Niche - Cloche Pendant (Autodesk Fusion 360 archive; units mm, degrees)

design "Cloche" references "Niche - Chief Architect - Luxe Single Pendant Cordset", "Cloche", "Luxe Single Pendant Cordset - 4ft Standard"
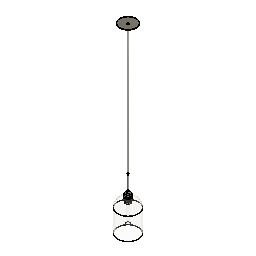
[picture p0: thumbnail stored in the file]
external_derived "ExternalDerived1" bodies "Cloche"
external_derived "ExternalDerived2" bodies "Socket Body", "Shade Ring", "Shade Ring +Collar", "Socket", "Body1", "Metal Strain Relief", "Fabric Cord (1)", "Stem (Threaded)"
align "Align1"
external_derived "ExternalDerived3" bodies "T9-Bulb"
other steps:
derived_base_feature "Derived Base Feature1" bodies "Cloche"
derived_base_feature "Derived Base Feature2" bodies "Socket Body", "Shade Ring", "Shade Ring +Collar", "Socket", "Body1", "Metal Strain Relief", "Fabric Cord (1)", "Stem (Threaded)"
derived_base_feature "Derived Base Feature3" bodies "T9-Bulb"
named bodies: "Cloche", "Socket Body", "Shade Ring", "Shade Ring +Collar", "Socket", "Body1", "Metal Strain Relief", "Fabric Cord (1)", "Stem (Threaded)", "Cap (Threaded)", "5M Set Screw", "T9-Bulb"

design "Luxe Single Pendant Cordset - 4ft Standard" references "Luxe Canopy - Single Pendant Cordset"
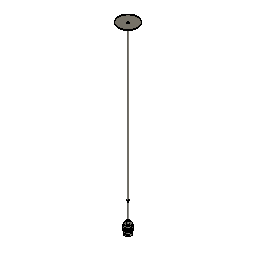
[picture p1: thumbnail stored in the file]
external_derived "ExternalDerived2" bodies "Cap (Threaded)"
move "Move1"
move "Move2"
offset_faces "OffsetFaces1" distance 1051.56
move "Move3"
move "Move4"
move "Move5"
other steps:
derived_base_feature "Derived Base Feature9" bodies "Socket Body", "Shade Ring", "Shade Ring +Collar", "Socket"
derived_base_feature "Derived Base Feature10" bodies "Body1"
derived_base_feature "Derived Base Feature12" bodies "Metal Strain Relief"
derived_base_feature "Derived Base Feature13" bodies "Fabric Cord (1)"
derived_base_feature "Derived Base Feature14" bodies "Stem (Threaded)"
derived_base_feature "Derived Base Feature15" bodies "Cap 9Threaded)", "Cap (Threaded)"
named bodies: "Socket Body", "Shade Ring", "Shade Ring +Collar", "Socket", "Metal Strain Relief", "Fabric Cord (1)", "Stem (Threaded)", "Cap 9Threaded)", "Body1", "Cap (Threaded)", "5M Set Screw"

design "Luxe Canopy - Single Pendant Cordset" references "M5 Set Screw", "Canopy Mounting Bar", "Canopy Mounting Bar Screw", "Plastic Strain Relief", "Luxe Cordset"
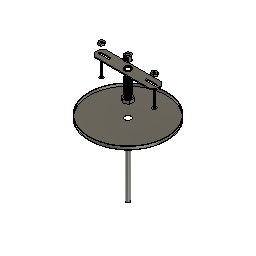
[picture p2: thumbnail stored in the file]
sketch "Sketch1" plane through (0, 0, 0) normal (0, 0, 1) x axis (1, 0, 0)
  circle C1 centre (0, 0) radius 63.5
  point P1 (0, 0)
  point P2 (0, 0)
  coincident P1 P2
  dimension "d1" diameter C1 = 127
extrude "Extrude1" new body sketch "Sketch1" along normal blind 5.08
shell "Shell1" innerThickness 0.762
hole "Hole1" HoleDepth 35.56 HoleDiameter 10.16 TipAngle 118
component_from_bodies "Body->Comp1"
component_insert "Component Insert1"
component_insert "Component Insert2"
component_insert "Component Insert3"
sketch "Sketch2" plane through (0, 0, 0) normal (0, 0, 1) x axis (1, 0, 0)
  circle C1 centre (0, 0) radius 3.175
  point P1 (0, 0)
  point P2 (0, 0)
  coincident P1 P2
  dimension "d8" diameter C1 = 6.35
extrude "Extrude2" new body sketch "Sketch2" along normal blind 127 and against normal blind 127 bodies "Fabric Cord"
component_insert "Component Insert4"
component_insert "Component Insert5"
position "Position1"
sketch "Sketch3" plane through (0, 0, 0.762) normal (0, 0, 1) x axis (-1, 0, 0)
  circle C1 centre (-0.0475, 0.2257) radius 5.08
  circle C2 centre (0, 0) radius 62.738
  circle C3 centre (0, 0) radius 4.826
  concentric C2 C3
  dimension "d13" diameter C3 = 9.652
extrude "Extrude3" new body sketch "Sketch3" profile of C3 along normal blind 25.4 bodies "Threaded Nipple"
shell "Shell2" innerThickness 1.27
thread "Thread1"
sketch "Sketch5" plane through (0, 0, 127) normal (0, 0, 1) x axis (-1, 0, 0)
  line L1 (-6.8191, 3.937) -> (0, 7.874)
  line L2 (-6.8191, -3.937) -> (-6.8191, 3.937)
  line L3 (0, -7.874) -> (-6.8191, -3.937)
  line L4 (6.8191, -3.937) -> (0, -7.874)
  line L5 (6.8191, 3.937) -> (6.8191, -3.937)
  line L6 (0, 7.874) -> (6.8191, 3.937)
  circle C1 centre (0, 0) radius 3.175
  point P2 (0, 0)
  point P9 (0, 0)
  point P3 (0, 7.874)
  coincident P2 P9
  dimension "d20" distance P3 P9 = 7.874
extrude "Extrude4" new body sketch "Sketch5" along normal blind 5.08 bodies "Hex Nut"
move "Move1"
thread "Thread2"
move "Move2" TranslateX 0 TranslateY 0 TranslateZ -55.88
move "Move3" TranslateX 0 TranslateY 0 TranslateZ 60.96
position "Position2"
sketch "Sketch6" plane through (0, 0, 0) normal (0, 0, 1) x axis (1, 0, 0)
  circle C1 centre (0, 0) radius 9.525
  point P1 (0, 0)
  point P2 (0, 0)
  coincident P1 P2
  dimension "d29" diameter C1 = 19.05
extrude "Extrude5" new body sketch "Sketch6" along normal blind 16.129 bodies "Metal Strain Relief"
move "Move4" TranslateX 0 TranslateY 0 TranslateZ -86.36
hole "Hole2" HoleDepth 10.16 HoleDiameter 5.08 TipAngle 118
hole "Hole3" HoleDepth 4.064 HoleDiameter 7.62 TipAngle 180
hole "Hole4" HoleDepth 12.192 HoleDiameter 9.144 TipAngle 180
thread "Thread3" ThreadOffset 0 ThreadLength 6.096
move "Move1" TranslateX 0 TranslateY 0 TranslateZ 68.58
move "Move5" TranslateX 0 TranslateY 0 TranslateZ 138.43
component_insert "Component Insert6"
external_derived "ExternalDerived1" bodies "5M Set Screw"
move "Move6" TranslateX 0 TranslateY 0 TranslateZ -185.42
copy_paste_bodies "CopyPasteBodies1"
move "Move7" TranslateX 0 TranslateY 0 TranslateZ -12.7
offset_faces "OffsetFaces1" distance -152.4
move "Move8"
component_from_bodies "Body->Comp2"
component_from_bodies "Body->Comp3"
component_from_bodies "Body->Comp4"
component_from_bodies "Body->Comp5"
hole "Hole1" HoleDepth 25.4 HoleDiameter 6.35 TipAngle 180
sketch "Sketch7" plane through (0, 0, 0) normal (0, 0, 1) x axis (1, 0, 0)
  line L1 (49.784, 3.9595) -> (52.07, 0)
  line L2 (45.212, 3.9595) -> (49.784, 3.9595)
  line L3 (42.926, 0) -> (45.212, 3.9595)
  line L4 (45.212, -3.9595) -> (42.926, 0)
  line L5 (49.784, -3.9595) -> (45.212, -3.9595)
  line L6 (52.07, 0) -> (49.784, -3.9595)
  point P2 (52.07, 0)
  point P8 (47.498, 0)
  dimension "d63" distance P2 P8 = 4.572
extrude "Extrude6" new body sketch "Sketch7" along normal blind 3.175 bodies "Mounting Hex Nut"
hole "Hole5" HoleDepth 25.4 HoleDiameter 3.81 TipAngle 180
thread "Thread4"
move "Move9"
component_from_bodies "Body->Comp6"
copy_paste "CopyPaste1"
move "Move10"
derived_base_feature "Derived Base Feature3" bodies "Stem (Threaded)", "Cap 9Threaded)"
move "Move11"
component_from_bodies "Body->Comp7"
component_from_bodies "Body->Comp8"
component_from_bodies "Body->Comp9"
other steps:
base_feature "Base Feature1"
base_feature "Base Feature1" bodies "Stem (Threaded)"
base_feature "Base Feature1" bodies "Cap 9Threaded)"
base_feature "Base Feature1" bodies "Fabric Cord"
base_feature "Base Feature1" bodies "Metal Strain Relief"
base_feature "Base Feature1" bodies "Mounting Hex Nut"
base_feature "Base Feature1" bodies "Hex Nut"
base_feature "Base Feature1" bodies "Fabric Cord (1)"
base_feature "Base Feature1" bodies "Threaded Nipple"
derived_base_feature "Derived Base Feature1" bodies "Socket Body", "Shade Ring", "Shade Ring +Collar", "Socket", "Rigid Stem"
derived_base_feature "Derived Base Feature2" bodies "5M Set Screw"
base_feature "Base Feature1" bodies "Fabric Cord", "Fabric Cord (1)"
create_component "CreateComponent1"
remove_body "RemoveBody1"
create_component "CreateComponent2"
remove_body "RemoveBody2"
create_component "CreateComponent3"
remove_body "RemoveBody3"
create_component "CreateComponent4"
remove_body "RemoveBody4"
create_component "CreateComponent5"
remove_body "RemoveBody5"
create_component "CreateComponent6"
remove_body "RemoveBody6"
create_component "CreateComponent7"
remove_body "RemoveBody7"
create_component "CreateComponent8"
remove_body "RemoveBody8"
create_component "CreateComponent9"
remove_body "RemoveBody9"
named bodies: "Fabric Cord", "Threaded Nipple", "Hex Nut", "Metal Strain Relief", "Socket Body", "Shade Ring", "Shade Ring +Collar", "Socket", "Rigid Stem", "5M Set Screw", "Fabric Cord (1)", "Mounting Hex Nut", "Stem (Threaded)", "Cap 9Threaded)"

design "M5 Set Screw"
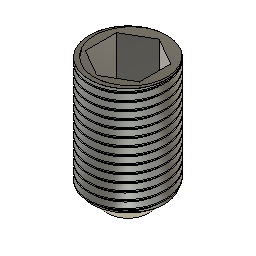
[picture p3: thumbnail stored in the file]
sketch "Sketch1" plane through (0, 0, 0) normal (0, 0, 1) x axis (1, 0, 0)
  circle C1 centre (0, 0) radius 2.5
  point P1 (0, 0)
  point P2 (0, 0)
  coincident P1 P2
  dimension "d1" diameter C1 = 5
extrude "Extrude1" new body sketch "Sketch1" along normal blind 8
sketch "Sketch2" plane through (0, 0, 8) normal (0, 0, 1) x axis (-1, 0, 0)
  line L1 (-1.7321, 1) -> (0, 2)
  line L2 (-1.7321, -1) -> (-1.7321, 1)
  line L3 (0, -2) -> (-1.7321, -1)
  line L4 (1.7321, -1) -> (0, -2)
  line L5 (1.7321, 1) -> (1.7321, -1)
  line L6 (0, 2) -> (1.7321, 1)
  circle C1 centre (0, 0) radius 2.5
  point P2 (0, 0)
  point P9 (0, 0)
  coincident P2 P9
extrude "Extrude2" cut sketch "Sketch2" profile of L1 L2 L3 L4 L5 L6 against normal blind 3
thread "Thread1" ThreadOffset 0.99 ThreadLength 7
chamfer "Chamfer1" distance 1.15

design "Luxe Cordset" references "M5 Set Screw"
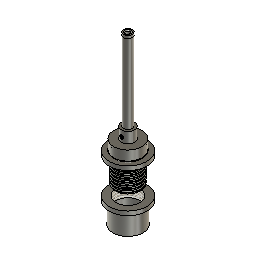
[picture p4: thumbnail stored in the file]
sketch "Sketch1" plane through (0, 0, 0) normal (0, 0, 1) x axis (1, 0, 0)
  circle C1 centre (0, 0) radius 20.6
  point P1 (0, 0)
  point P2 (0, 0)
  coincident P1 P2
  dimension "d11" diameter C1 = 41.2
extrude "Extrude1" new body sketch "Sketch1" along normal blind 14 bodies "Socket Body"
sketch "Sketch2" plane through (0, 0, 14) normal (0, 0, 1) x axis (-1, 0, 0)
  circle C1 centre (0, 0) radius 20.6
  circle C2 centre (0, 0) radius 9.6
  concentric C1 C2
  dimension "d3" diameter C2 = 19.2
extrude "Extrude2" add sketch "Sketch2" profile of C2 along normal blind 15.75
sketch "Sketch3" plane through (0, 0, 29.75) normal (0, 0, 1) x axis (-1, 0, 0)
  circle C1 centre (0, 0) radius 9.6
  circle C2 centre (0, 0) radius 5.75
  concentric C1 C2
  dimension "d6" diameter C2 = 11.5
extrude "Extrude3" new body sketch "Sketch3" profile of C2 along normal blind 114 bodies "Rigid Stem"
move "Move1"
sketch "Sketch4" plane through (0, 0, 203.75) normal (0, 0, 1) x axis (-1, 0, 0)
  circle C1 centre (0, 0) radius 5.75
  circle C2 centre (0, 0) radius 27.5
  dimension "d10" diameter C2 = 55
extrude "Extrude4" new body sketch "Sketch4" profile of C2 along normal blind 6 bodies "Shade Ring"
hole "Hole1" HoleDepth 25 HoleDiameter 42.75 TipAngle 118
sketch "Sketch5" plane through (0, 0, 0) normal (0, 0, 1) x axis (1, 0, 0)
  circle C1 centre (0, 0) radius 22
  point P1 (0, 0)
  point P2 (0, 0)
  coincident P1 P2
  dimension "d18" diameter C1 = 44
move "Move2"
copy_paste_bodies "CopyPasteBodies1"
move "Move3"
sketch "Sketch6" plane through (0, 0, 60) normal (0, 0, -1) x axis (1, 0, 0)
  circle C1 centre (0, 0) radius 20.6
  circle C2 centre (0, 0) radius 21.375
  circle C3 centre (0, 0) radius 20
  concentric C1 C2
  concentric C1 C3
  dimension "d21" diameter C2 = 42.75
  dimension "d24" diameter C3 = 40
cylinder_primitive "CylinderPrimitive1" Height 8 Diameter 42.75
thread "Thread1"
thread "Thread3"
hole "Hole2" HoleDepth 18 HoleDiameter 39 TipAngle 180
move "Move4"
move "Move5"
move "Move6"
hole "Hole3" HoleDepth 114 HoleDiameter 7.6 TipAngle 180
derived_base_feature "Derived Base Feature" bodies "Socket"
move "Move7"
scale "Scale1" ScaleX 1.2 ScaleY 1.2
move "Move8"
sketch "Sketch8" plane through (0, 0, -23.9827) normal (0, 0, -1) x axis (1, 0, 0)
  circle C1 centre (0, -0.036) radius 27.5
  circle C2 centre (0, -0.036) radius 22
  circle C3 centre (0, -0.036) radius 19.5
  dimension "d36" diameter C2 = 44
  dimension "d42" = -2.5
extrude "Extrude7" add sketch "Sketch8" profile of C2 C3 along normal blind 30
offset_faces "OffsetFaces1" distance 2.75
offset_faces "OffsetFaces2" distance -9
thread "Thread2"
move "Move9"
move "Move10"
move "Move11"
scale "Scale2" ScaleZ 1.2
move "Move12"
move "Move13"
move "Move14"
move "Move15"
move "Move16"
split_face "SplitFace1"
move "Move17"
move "Move18"
move "Move19"
move "Move20"
move "Move21"
move "Move22"
move "Move23"
move "Move24"
move "Move25"
move "Move26"
move "Move27"
thread "Thread4"
move "Move28"
move "Move29"
move "Move30"
hole "Hole4" HoleDepth 21 HoleDiameter 39.35 TipAngle 180
hole "Hole5" HoleDepth 9 HoleDiameter 5 TipAngle 180
move "Move31"
move "Move32"
hole "Hole6" HoleDepth 20 HoleDiameter 10 TipAngle 180
move_face "MoveFace3"
move "Move33"
move "Move34"
move "Move35"
move "Move36"
move "Move37"
thread "Thread5" ThreadOffset 0 ThreadLength 6
thread "Thread6" ThreadOffset 0 ThreadLength 6
move "Move38"
move "Move39"
move "Move40"
move "Move41"
component_insert "Component Insert"
thread "Thread7" ThreadOffset 0.5 ThreadLength 5.337
chamfer "Chamfer1" distance 0.5 distance 0.35
sketch "Sketch12" plane through (0, 0, 0) normal (0, 0, 1) x axis (1, 0, 0)
  circle C1 centre (0, 0) radius 6.35
  dimension "d60" diameter C1 = 12.7
extrude "Extrude8" new body sketch "Sketch12" along normal blind 115 bodies "Stem (Threaded)"
hole "Hole7" HoleDepth 115 HoleDiameter 9.65 TipAngle 118
thread "Thread8" ThreadOffset 0 ThreadLength 12.5
thread "Thread9" ThreadOffset 0 ThreadLength 12.5
sketch "Sketch13" plane through (0, 0, 0) normal (0, 0, 1) x axis (1, 0, 0)
  circle C1 centre (0, 0) radius 6.35
  point P1 (0, 0)
  point P2 (0, 0)
  coincident P1 P2
  dimension "d70" diameter C1 = 12.7
extrude "Extrude9" new body sketch "Sketch13" along normal blind 4 bodies "Cap 9Threaded)"
sketch "Sketch14" plane through (0, 0, 4) normal (0, 0, 1) x axis (-1, 0, 0)
  circle C1 centre (0, 0) radius 6.35
  circle C2 centre (0, 0) radius 4.5
  concentric C1 C2
  dimension "d73" diameter C2 = 9
extrude "Extrude10" add sketch "Sketch14" profile of C2 against normal blind 14
thread "Thread10"
hole "Hole8" HoleDepth 115 HoleDiameter 6.5 TipAngle 118 CSDiameter 9 CSAngle 90
move "Move42"
move "Move43"
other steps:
base_feature "Base Feature" bodies "Shade Ring +Collar"
named bodies: "Socket Body", "Shade Ring", "Shade Ring +Collar", "Socket", "Rigid Stem", "Stem (Threaded)", "Cap 9Threaded)"

design "Niche - Chief Architect - Luxe Single Pendant Cordset"
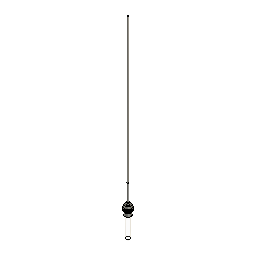
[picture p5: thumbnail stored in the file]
derived_base_feature "Derived Base Feature" bodies "Socket Body", "Shade Ring", "Shade Ring +Collar", "Socket", "Canopy", "Metal Strain Relief", "Fabric Cord (1)", "Stem (Threaded)"
remove_body "RemoveBody1"
remove_body "RemoveBody2"
split "Split1" bodies "Socket Body (1)"
remove_body "RemoveBody3"
align "Align1"
hole "Hole1" HoleDepth 19.05 HoleDiameter 8.89 TipAngle 118
combine "Combine1" bodies "Shade Ring"
split "Split2" bodies "Socket (1)"
remove_body "RemoveBody4"
split "Split3" bodies "Fabric Cord (1) (1)"
remove_body "RemoveBody5"
combine "Combine2" bodies "Socket Body"
align "Align2"
combine "Combine3" bodies "Metal Strain Relief"
sketch "Sketch1" plane through (0, 0, 0) normal (0, 1, 0) x axis (1, 0, 0)
  line L1 (13.1098, 24.9049) -> (-12.2902, 24.9049)
  line L2 (18.1898, 37.1766) -> (18.1898, 29.9849)
  line L3 (-17.3702, 29.9849) -> (-17.3702, 36.7132)
  line L4 (0, 132.969) -> (0, 24.9049)
  arc A1 centre (0, 86.36) radius 46.609 clockwise from (-22.6031, 45.5985) to (23.276, 45.979)
  arc A2 centre (-27.5302, 36.7132) radius 10.16 clockwise from (-22.6031, 45.5985) to (-17.3702, 36.7132)
  arc A3 centre (28.3498, 37.1766) radius 10.16 clockwise from (18.1898, 37.1766) to (23.276, 45.979)
  arc A4 centre (-12.2902, 29.9849) radius 5.08 clockwise from (-12.2902, 24.9049) to (-17.3702, 29.9849)
  arc A5 centre (13.1098, 29.9849) radius 5.08 clockwise from (18.1898, 29.9849) to (13.1098, 24.9049)
  point P5 (18.1898, 43.4469)
  point P3 (-17.3702, 24.9049)
  point P4 (18.1898, 24.9049)
  point P18 (0, 24.9049)
  point P19 (0, 132.969)
  horizontal L1
  vertical L2
  vertical L3
  tangent A1 A2
  tangent L3 A2
  coincident P5 L2
  coincident P5 A1
  tangent L2 A3
  tangent A1 A3
  equal A2 A3
  coincident P3 L1
  coincident P3 L3
  tangent L1 A4
  tangent L3 A4
  coincident P4 L1
  coincident P4 L2
  tangent L1 A5
  tangent L2 A5
  coincident L1 P18
  coincident A1 P19
  perpendicular L1 L4
  dimension "d4" diameter A1 = 93.218
  dimension "d5" distance P3 P4 = 35.56
  dimension "d6" distance P4 P5 = 18.542
  dimension "d7" radius A2 = 10.16
  dimension "d8" radius A4 = 5.08
  dimension "d9" radius A5 = 5.08
revolve "Revolve1" sketch "Sketch1" AlongAngle 360 bodies "G30-Bulb"
move "Move1"
sketch "Sketch2" plane through (0, 0, 0) normal (0, 1, 0) x axis (1, 0, 0)
  line L1 (12.7, 0) -> (-12.7, 0)
  line L2 (12.7, 152.4) -> (12.7, 0)
  line L3 (-12.7, 0) -> (-12.7, 152.4)
  line L4 (0, 165.1) -> (0, 0)
  arc A1 centre (0, 152.4) radius 12.7 clockwise from (-12.7, 152.4) to (12.7, 152.4)
  point P1 (0, 0)
  point P7 (0, 0)
  point P8 (0, 165.1)
  horizontal L1
  vertical L2
  vertical L3
  coincident P1 P7
  midpoint A1 P8
  perpendicular L1 L4
revolve "Revolve2" sketch "Sketch2" AlongAngle 360 bodies "T9-Bulb"
move "Move2"
sketch "Sketch3" plane through (0, 0, 0) normal (0, 1, 0) x axis (1, 0, 0)
  line L1 (12.7, 0) -> (-12.7, 0)
  line L2 (12.7, 254) -> (12.7, 0)
  line L3 (-12.7, 0) -> (-12.7, 254)
  line L4 (0, 266.7) -> (0, 0)
  arc A1 centre (0, 254) radius 12.7 clockwise from (-12.7, 254) to (12.7, 254)
  point P1 (0, 0)
  point P7 (0, 0)
  point P8 (0, 266.7)
  horizontal L1
  vertical L2
  vertical L3
  coincident P1 P7
  midpoint A1 P8
  perpendicular L1 L4
revolve "Revolve3" sketch "Sketch3" AlongAngle 360 bodies "T8-Bulb"
move "Move3"
move "Move4"
move "Move5"
sketch "Sketch4" plane through (0, 0, 0) normal (0, 1, 0) x axis (1, 0, 0)
  line L1 (15.875, -8.763) -> (-15.875, -8.763)
  line L2 (15.875, 22.987) -> (15.875, -8.763)
  line L3 (-15.875, 22.987) -> (15.875, 22.987)
  line L4 (-15.875, -8.763) -> (-15.875, 22.987)
  line L5 (0, 22.987) -> (0, -8.763)
  point P6 (0, -8.763)
  point P7 (0, 22.987)
  point P2 (-15.875, -8.763)
  point P3 (15.875, -8.763)
  point P5 (-15.875, 22.987)
  horizontal L1
  vertical L2
  horizontal L3
  vertical L4
  midpoint L1 P6
  midpoint L3 P7
  dimension "d13" distance P2 P3 = 31.75
  dimension "d14" distance P2 P5 = 31.75
revolve "Revolve4" sketch "Sketch4" AlongAngle 360 bodies "Bulb Extender"
move "Move6"
sketch "Sketch5" plane through (0, 0, 0) normal (0, 1, 0) x axis (1, 0, 0)
  line L1 (-12.7, 35.56) -> (12.7, 35.56)
  line L2 (-12.7, 5.08) -> (-12.7, 35.56)
  line L3 (12.7, 5.08) -> (-12.7, 5.08)
  line L4 (12.7, 35.56) -> (12.7, 5.08)
  line L5 (-12.7, 5.08) -> (12.7, 35.56)
  line L6 (12.7, 5.08) -> (-12.7, 35.56)
  line L7 (0, 35.56) -> (0, 5.08)
  point P6 (0, 20.32)
  point P7 (0, 5.08)
  point P8 (0, 35.56)
  horizontal L1
  perpendicular L1 L2
  parallel L1 L3
  parallel L2 L4
  coincident L5 P6
  coincident L6 P6
  midpoint L3 P7
  midpoint L1 P8
revolve "Revolve5" sketch "Sketch5" AlongAngle 360 bodies "Y-Spliter"
sketch "Sketch6" plane through (0, 0, 0) normal (0, 1, 0) x axis (1, 0, 0)
  line L1 (-55.88, 64.9514) -> (-21.59, 64.9514)
  line L2 (-55.88, 35.7414) -> (-55.88, 64.9514)
  line L3 (-21.59, 35.7414) -> (-55.88, 35.7414)
  line L4 (-21.59, 64.9514) -> (-21.59, 35.7414)
  line L5 (-55.88, 35.7414) -> (-21.59, 64.9514)
  line L6 (-21.59, 35.7414) -> (-55.88, 64.9514)
  line L7 (-38.735, 64.9514) -> (-38.735, 35.7414)
  point P6 (-38.735, 50.3464)
  point P7 (-38.735, 35.7414)
  point P8 (-38.735, 64.9514)
  point P4 (-55.88, 35.7414)
  point P5 (-21.59, 35.7414)
  point P2 (-21.59, 64.9514)
  horizontal L1
  perpendicular L1 L2
  parallel L1 L3
  parallel L2 L4
  coincident L5 P6
  coincident L6 P6
  midpoint L3 P7
  midpoint L1 P8
  dimension "d17" distance P4 P5 = 34.29
  dimension "d18" distance P2 P5 = 29.21
revolve "Revolve6" sketch "Sketch6" AlongAngle 360
chamfer "Chamfer1" distance 7.62
move "Move7"
mirror "Mirror1" mirrorStitchTolerance 0.1016
move "Move8"
combine "Combine4"
move "Move9"
sketch "Sketch7" plane through (0, 0, 0) normal (0, 1, 0) x axis (1, 0, 0)
  line L1 (-15.24, 40.64) -> (-15.24, 48.1816)
  line L2 (12.7, 38.1) -> (-12.7, 38.1)
  line L3 (15.24, 48.1816) -> (15.24, 40.64)
  line L4 (0, 100.1623) -> (0, 38.1)
  arc A1 centre (0, 76.2) radius 23.9623 clockwise from (-19.7282, 62.5988) to (19.7282, 62.5988)
  arc A2 centre (-40.64, 48.1816) radius 25.4 clockwise from (-19.7282, 62.5988) to (-15.24, 48.1816)
  arc A3 centre (40.64, 48.1816) radius 25.4 clockwise from (15.24, 48.1816) to (19.7282, 62.5988)
  arc A4 centre (-12.7, 40.64) radius 2.54 clockwise from (-12.7, 38.1) to (-15.24, 40.64)
  arc A5 centre (12.7, 40.64) radius 2.54 clockwise from (15.24, 40.64) to (12.7, 38.1)
  point P15 (0, 38.1)
  point P16 (0, 100.1623)
  parallel L1 L3
  tangent A1 A2
  tangent L1 A2
  tangent A1 A3
  tangent L3 A3
  tangent L1 A4
  tangent L2 A4
  tangent L2 A5
  tangent L3 A5
  midpoint L2 P15
  midpoint A1 P16
  perpendicular L2 L4
  dimension "d23" radius A2 = 25.4
  dimension "d24" radius A3 = 25.4
  dimension "d25" radius A4 = 2.54
  dimension "d26" radius A5 = 2.54
revolve "Revolve7" sketch "Sketch7" AlongAngle 360 bodies "A15-Bulb"
move "Move10"
copy_paste_bodies "CopyPasteBodies1"
copy_paste_bodies "CopyPasteBodies2"
move "Move11"
mirror "Mirror2" mirrorStitchTolerance 0.1016 bodies "A15-Bulb (1) (1)"
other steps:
base_feature "Base Feature1" bodies "Y-Spliter", "Bulb Extender", "Y-Spliter (1)", "Bulb Extender (1)"
base_feature "Base Feature2" bodies "A15-Bulb", "A15-Bulb (1)"
named bodies: "Socket Body", "Shade Ring", "Shade Ring +Collar", "Socket", "Canopy", "Metal Strain Relief", "Fabric Cord (1)", "Stem (Threaded)", "Adapter", "5M Set Screw", "Body1 (1)", "Socket Body (1)", "Socket (1)", "Fabric Cord (1) (1)", "G30-Bulb", "T9-Bulb", "T8-Bulb", "Bulb Extender", "Y-Spliter", "A15-Bulb", "Y-Spliter (1)", "Bulb Extender (1)", "A15-Bulb (1)", "A15-Bulb (1) (1)"

design "Plastic Strain Relief"
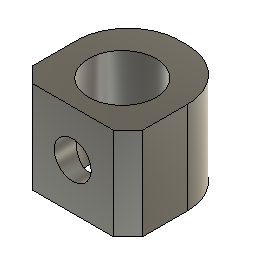
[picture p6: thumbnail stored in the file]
base_feature "Base Feature" bodies "strainrelief"
named bodies: "strainrelief"

design "Cloche"
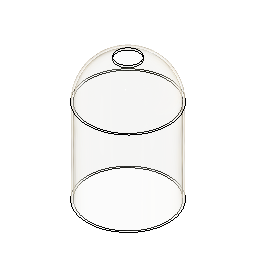
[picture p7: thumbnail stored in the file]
sketch "Sketch1" plane through (0, 0, 0) normal (0, 1, 0) x axis (1, 0, 0)
  line L1 (0, 171.45) -> (0, -82.55)
  line L2 (82.55, 171.45) -> (82.55, 0)
  line L3 (-82.55, 171.45) -> (-82.55, 0)
  line L4 (78.74, 171.45) -> (78.74, 0)
  line L5 (-78.74, 171.45) -> (-78.74, 0)
  line L6 (-78.74, 171.45) -> (-82.55, 171.45)
  line L7 (82.55, 171.45) -> (78.74, 171.45)
  line L8 (22.225, -75.5383) -> (22.225, -79.5019)
  line L9 (-22.225, -75.5383) -> (-22.225, -79.5019)
  arc A1 centre (0, 0) radius 82.55 clockwise from (-22.225, -79.5019) to (-82.55, 0)
  arc A2 centre (0, 0) radius 82.55 clockwise from (82.55, 0) to (22.225, -79.5019)
  arc A3 centre (0, 0) radius 78.74 clockwise from (-22.225, -75.5383) to (-78.74, 0)
  arc A4 centre (0, 0) radius 78.74 clockwise from (78.74, 0) to (22.225, -75.5383)
  point P2 (0, -82.55)
  point P14 (22.225, -75.5383)
  coincident P2 A1
  parallel L1 L2
  parallel L1 L3
  perpendicular L2 L6
  collinear L6 L7
  parallel L1 L9
  parallel L1 L8
  coincident P14 A3
  concentric A1 A2
  parallel L2 L4
  parallel L3 L5
  tangent L5 A3
  tangent L4 A3
  concentric A3 A4
  dimension "d1" diameter A1 = 165.1
revolve "Revolve1" sketch "Sketch1" AlongAngle 360 bodies "Cloche"
named bodies: "Cloche"

design "Canopy Mounting Bar Screw"
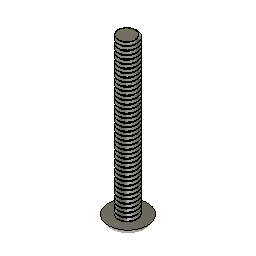
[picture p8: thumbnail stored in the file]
base_feature "Base Feature" bodies "screw1"
named bodies: "screw1"

design "Canopy Mounting Bar"
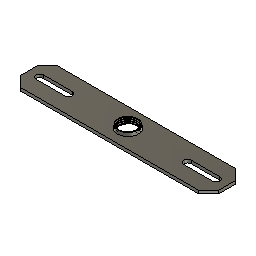
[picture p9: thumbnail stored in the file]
base_feature "Base Feature" bodies "mountingbar"
named bodies: "mountingbar"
